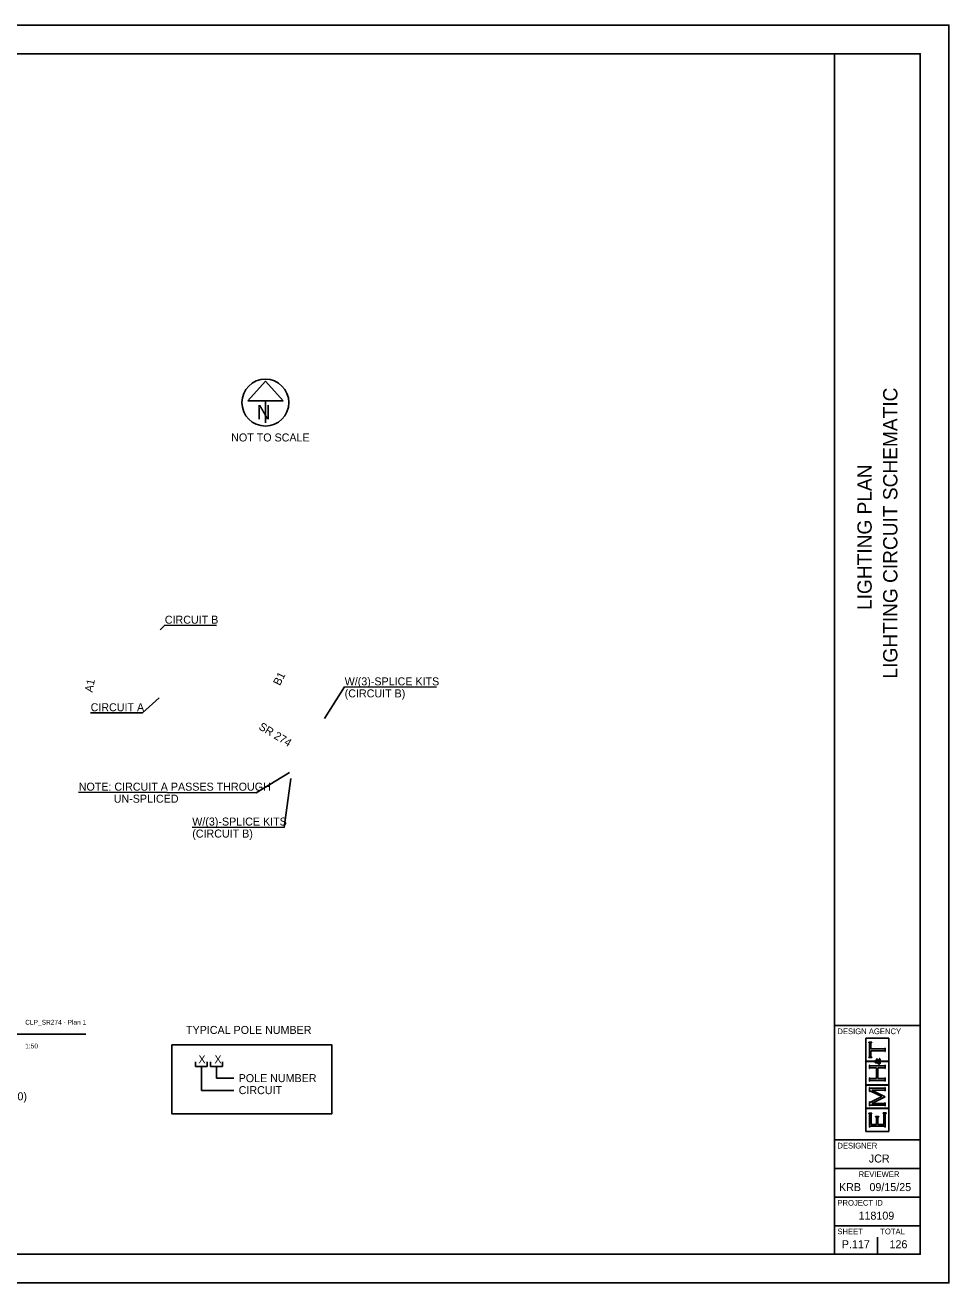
# Model space of a CAD drawing. Extents: x 0 to 34, y 0 to 22.
# Drawn here: x 17.84 to 34, y 0 to 22 of the extents above; entities that cross this region are included whole.
import ezdxf

# ---------------------------------------------------------------- set-up
doc = ezdxf.new("R2010")
doc.units = 0
for name, color, linetype in [('_CIVIL_CONSTRUCTION', 7, 'Continuous'), ('GE_P_Alignment', 7, 'Continuous'), ('PF_P_Grade_Line', 7, 'Continuous'), ('PF_X_Ground_Line', 7, 'Continuous'), ('SC_Scratch1', 7, 'Continuous'), ('SC_Scratch7', 7, 'Continuous')]:
    doc.layers.add(name, color=color, linetype=linetype)

msp = doc.modelspace()

# ---------------------------------------------------------------- linework, layer by layer
at = {"layer": '_CIVIL_CONSTRUCTION'}
for p, q in [((32, 0.5), (32, 21.5)), ((32, 4.5), (33.5, 4.5)), ((32, 2.5), (33.5, 2.5)), ((32, 2), (33.5, 2)), ((32, 1.5), (33.5, 1.5)), ((32, 1), (33.5, 1))]:
    msp.add_line(p, q, dxfattribs=at)
msp.add_lwpolyline([(1.5, 21.5), (33.5, 21.5), (33.5, 0.5), (1.5, 0.5)], close=True, dxfattribs=at)
at = {"layer": 'GE_P_Alignment'}
msp.add_lwpolyline([(0, 0), (34, 0), (34, 22), (0, 22)], close=True, dxfattribs=at)
at = {"layer": 'PF_P_Grade_Line'}
for p, q in [((22.043, 15.772), (21.735, 15.431)), ((22.35, 15.43), (22.043, 15.772)), ((21.735, 15.431), (22.35, 15.43)), ((22.042, 15.43), (22.041, 15.044)), ((20.28, 11.503), (20.201, 11.422)), ((21.188, 11.5), (20.28, 11.503)), ((23.427, 10.424), (23.078, 9.874)), ((25.037, 10.419), (23.427, 10.424)), ((19.89, 9.968), (20.185, 10.235)), ((19.89, 9.968), (18.982, 9.971)), ((21.881, 8.569), (22.463, 8.926)), ((22.37, 7.967), (22.486, 8.823)), ((21.881, 8.569), (18.774, 8.582)), ((22.37, 7.967), (20.759, 7.971)), ((20.818, 3.867), (20.818, 3.786)), ((20.818, 3.786), (21.025, 3.786)), ((20.921, 3.786), (20.921, 3.363)), ((21.025, 3.867), (21.025, 3.786)), ((21.084, 3.865), (21.084, 3.784)), ((21.084, 3.784), (21.29, 3.784)), ((21.187, 3.784), (21.187, 3.578)), ((21.29, 3.865), (21.29, 3.784)), ((21.187, 3.578), (21.488, 3.578)), ((20.921, 3.363), (21.488, 3.363))]:
    msp.add_line(p, q, dxfattribs=at)
msp.add_lwpolyline([(20.407, 4.166), (23.202, 4.166), (23.202, 2.955), (20.407, 2.955)], close=True, dxfattribs=at)
msp.add_circle((22.042, 15.398), 0.41, dxfattribs=at)
at = {"layer": 'PF_X_Ground_Line'}
for p, q in [((32.952, 4.279), (32.547, 4.279)), ((32.547, 4.279), (32.547, 3.875)), ((32.598, 4.204), (32.598, 4.211)), ((32.598, 4.211), (32.65, 4.211)), ((32.603, 4.203), (32.598, 4.204)), ((32.606, 4.201), (32.603, 4.203)), ((32.608, 4.199), (32.606, 4.201)), ((32.61, 4.196), (32.608, 4.199)), ((32.611, 4.192), (32.61, 4.196)), ((32.611, 4.187), (32.611, 4.192)), ((32.611, 3.968), (32.611, 4.187)), ((32.638, 4.196), (32.637, 4.192)), ((32.637, 4.192), (32.637, 4.187)), ((32.637, 4.187), (32.637, 4.093)), ((32.64, 4.199), (32.638, 4.196)), ((32.642, 4.201), (32.64, 4.199)), ((32.645, 4.203), (32.642, 4.201)), ((32.65, 4.204), (32.645, 4.203)), ((32.65, 4.211), (32.65, 4.204)), ((32.952, 3.875), (32.952, 4.279)), ((32.61, 3.958), (32.611, 3.962)), ((32.611, 3.962), (32.611, 3.968)), ((32.637, 4.093), (32.864, 4.093)), ((32.864, 4.061), (32.637, 4.061)), ((32.637, 4.061), (32.637, 3.968)), ((32.637, 3.968), (32.637, 3.962)), ((32.637, 3.962), (32.638, 3.958)), ((32.864, 4.093), (32.869, 4.093)), ((32.87, 4.061), (32.864, 4.061)), ((32.869, 4.093), (32.873, 4.094)), ((32.874, 4.06), (32.87, 4.061)), ((32.873, 4.094), (32.876, 4.096)), ((32.876, 4.059), (32.874, 4.06)), ((32.876, 4.096), (32.878, 4.097)), ((32.878, 4.057), (32.876, 4.059)), ((32.878, 4.097), (32.88, 4.101)), ((32.88, 4.053), (32.878, 4.057)), ((32.88, 4.101), (32.881, 4.106)), ((32.881, 4.048), (32.88, 4.053)), ((32.881, 4.106), (32.888, 4.106)), ((32.888, 4.048), (32.881, 4.048)), ((32.888, 4.106), (32.888, 4.048)), ((32.547, 3.875), (32.696, 3.875)), ((32.696, 3.869), (32.547, 3.869)), ((32.547, 3.869), (32.547, 3.465)), ((32.598, 3.95), (32.603, 3.951)), ((32.598, 3.944), (32.598, 3.95)), ((32.65, 3.944), (32.598, 3.944)), ((32.603, 3.951), (32.606, 3.953)), ((32.606, 3.953), (32.608, 3.955)), ((32.608, 3.955), (32.61, 3.958)), ((32.611, 3.749), (32.611, 3.807)), ((32.611, 3.807), (32.617, 3.807)), ((32.617, 3.749), (32.611, 3.749)), ((32.617, 3.807), (32.619, 3.802)), ((32.618, 3.754), (32.617, 3.749)), ((32.62, 3.758), (32.618, 3.754)), ((32.619, 3.802), (32.62, 3.798)), ((32.62, 3.798), (32.623, 3.797)), ((32.623, 3.76), (32.62, 3.758)), ((32.623, 3.797), (32.625, 3.795)), ((32.625, 3.761), (32.623, 3.76)), ((32.625, 3.795), (32.629, 3.794)), ((32.629, 3.762), (32.625, 3.761)), ((32.629, 3.794), (32.635, 3.794)), ((32.635, 3.762), (32.629, 3.762)), ((32.635, 3.794), (32.864, 3.794)), ((32.732, 3.762), (32.635, 3.762)), ((32.638, 3.958), (32.64, 3.955)), ((32.64, 3.955), (32.642, 3.953)), ((32.642, 3.953), (32.645, 3.951)), ((32.645, 3.951), (32.65, 3.95)), ((32.65, 3.95), (32.65, 3.944)), ((32.696, 3.875), (32.696, 3.869)), ((32.703, 3.879), (32.705, 3.883)), ((32.703, 3.873), (32.703, 3.879)), ((32.703, 3.868), (32.703, 3.873)), ((32.705, 3.863), (32.703, 3.868)), ((32.705, 3.883), (32.708, 3.887)), ((32.708, 3.858), (32.705, 3.863)), ((32.708, 3.887), (32.711, 3.89)), ((32.709, 3.879), (32.708, 3.876)), ((32.708, 3.876), (32.708, 3.873)), ((32.708, 3.873), (32.708, 3.869)), ((32.708, 3.869), (32.71, 3.866)), ((32.712, 3.853), (32.708, 3.858)), ((32.712, 3.881), (32.709, 3.879)), ((32.71, 3.866), (32.712, 3.864)), ((32.711, 3.89), (32.715, 3.892)), ((32.714, 3.883), (32.712, 3.881)), ((32.712, 3.864), (32.715, 3.862)), ((32.718, 3.85), (32.712, 3.853)), ((32.716, 3.884), (32.714, 3.883)), ((32.715, 3.892), (32.72, 3.892)), ((32.715, 3.862), (32.718, 3.861)), ((32.72, 3.884), (32.716, 3.884)), ((32.718, 3.861), (32.721, 3.861)), ((32.726, 3.85), (32.718, 3.85)), ((32.72, 3.892), (32.725, 3.892)), ((32.724, 3.884), (32.72, 3.884)), ((32.721, 3.861), (32.723, 3.861)), ((32.723, 3.861), (32.725, 3.862)), ((32.728, 3.882), (32.724, 3.884)), ((32.725, 3.892), (32.729, 3.89)), ((32.725, 3.862), (32.728, 3.862)), ((32.729, 3.85), (32.726, 3.85)), ((32.731, 3.88), (32.728, 3.882)), ((32.728, 3.862), (32.731, 3.863)), ((32.729, 3.89), (32.732, 3.887)), ((32.731, 3.85), (32.729, 3.85)), ((32.734, 3.877), (32.731, 3.88)), ((32.731, 3.863), (32.735, 3.865)), ((32.734, 3.851), (32.731, 3.85)), ((32.732, 3.887), (32.736, 3.883)), ((32.732, 3.572), (32.732, 3.762)), ((32.737, 3.872), (32.734, 3.877)), ((32.737, 3.852), (32.734, 3.851)), ((32.735, 3.865), (32.74, 3.867)), ((32.736, 3.883), (32.74, 3.878)), ((32.74, 3.867), (32.737, 3.872)), ((32.741, 3.853), (32.737, 3.852)), ((32.738, 3.893), (32.738, 3.922)), ((32.738, 3.922), (32.741, 3.922)), ((32.741, 3.893), (32.738, 3.893)), ((32.74, 3.878), (32.744, 3.869)), ((32.741, 3.922), (32.741, 3.918)), ((32.741, 3.918), (32.742, 3.915)), ((32.742, 3.896), (32.741, 3.895)), ((32.741, 3.895), (32.741, 3.893)), ((32.746, 3.855), (32.741, 3.853)), ((32.742, 3.915), (32.743, 3.913)), ((32.743, 3.897), (32.742, 3.896)), ((32.743, 3.913), (32.745, 3.911)), ((32.745, 3.899), (32.743, 3.897)), ((32.744, 3.869), (32.754, 3.875)), ((32.745, 3.911), (32.749, 3.908)), ((32.746, 3.899), (32.745, 3.899)), ((32.748, 3.899), (32.746, 3.899)), ((32.752, 3.844), (32.746, 3.855)), ((32.755, 3.899), (32.748, 3.899)), ((32.749, 3.908), (32.756, 3.904)), ((32.756, 3.86), (32.751, 3.857)), ((32.751, 3.857), (32.754, 3.852)), ((32.757, 3.837), (32.752, 3.844)), ((32.754, 3.875), (32.764, 3.881)), ((32.754, 3.852), (32.757, 3.848)), ((32.763, 3.895), (32.755, 3.899)), ((32.756, 3.904), (32.763, 3.9)), ((32.761, 3.863), (32.756, 3.86)), ((32.757, 3.848), (32.761, 3.845)), ((32.763, 3.833), (32.757, 3.837)), ((32.864, 3.762), (32.759, 3.762)), ((32.759, 3.762), (32.759, 3.572)), ((32.764, 3.865), (32.761, 3.863)), ((32.761, 3.845), (32.765, 3.843)), ((32.763, 3.9), (32.77, 3.896)), ((32.772, 3.887), (32.763, 3.895)), ((32.768, 3.829), (32.763, 3.833)), ((32.764, 3.881), (32.772, 3.887)), ((32.768, 3.867), (32.764, 3.865)), ((32.765, 3.843), (32.769, 3.841)), ((32.774, 3.872), (32.768, 3.867)), ((32.774, 3.827), (32.768, 3.829)), ((32.769, 3.841), (32.773, 3.841)), ((32.77, 3.896), (32.776, 3.891)), ((32.773, 3.841), (32.778, 3.841)), ((32.782, 3.878), (32.774, 3.872)), ((32.779, 3.827), (32.774, 3.827)), ((32.776, 3.891), (32.781, 3.895)), ((32.778, 3.841), (32.782, 3.843)), ((32.779, 3.923), (32.781, 3.926)), ((32.782, 3.922), (32.779, 3.923)), ((32.785, 3.827), (32.779, 3.827)), ((32.781, 3.926), (32.787, 3.924)), ((32.781, 3.895), (32.784, 3.898)), ((32.785, 3.921), (32.782, 3.922)), ((32.786, 3.873), (32.782, 3.878)), ((32.782, 3.843), (32.786, 3.846)), ((32.784, 3.898), (32.786, 3.901)), ((32.786, 3.919), (32.785, 3.921)), ((32.79, 3.829), (32.785, 3.827)), ((32.788, 3.917), (32.786, 3.919)), ((32.786, 3.901), (32.788, 3.904)), ((32.791, 3.886), (32.786, 3.881)), ((32.786, 3.881), (32.791, 3.876)), ((32.788, 3.869), (32.786, 3.873)), ((32.786, 3.846), (32.789, 3.849)), ((32.787, 3.924), (32.792, 3.921)), ((32.789, 3.914), (32.788, 3.917)), ((32.788, 3.904), (32.789, 3.908)), ((32.79, 3.867), (32.788, 3.869)), ((32.789, 3.911), (32.789, 3.914)), ((32.789, 3.908), (32.789, 3.911)), ((32.789, 3.849), (32.791, 3.853)), ((32.791, 3.864), (32.79, 3.867)), ((32.793, 3.834), (32.79, 3.829)), ((32.794, 3.89), (32.791, 3.886)), ((32.791, 3.876), (32.795, 3.87)), ((32.791, 3.861), (32.791, 3.864)), ((32.791, 3.859), (32.791, 3.861)), ((32.791, 3.853), (32.791, 3.859)), ((32.792, 3.921), (32.795, 3.918)), ((32.797, 3.838), (32.793, 3.834)), ((32.796, 3.894), (32.794, 3.89)), ((32.795, 3.918), (32.798, 3.914)), ((32.795, 3.87), (32.797, 3.866)), ((32.798, 3.897), (32.796, 3.894)), ((32.797, 3.866), (32.798, 3.861)), ((32.799, 3.844), (32.797, 3.838)), ((32.798, 3.914), (32.799, 3.91)), ((32.799, 3.901), (32.798, 3.897)), ((32.798, 3.861), (32.799, 3.857)), ((32.799, 3.91), (32.799, 3.905)), ((32.799, 3.905), (32.799, 3.901)), ((32.803, 3.869), (32.799, 3.875)), ((32.799, 3.875), (32.952, 3.875)), ((32.799, 3.857), (32.799, 3.852)), ((32.799, 3.852), (32.799, 3.844)), ((32.952, 3.869), (32.803, 3.869)), ((32.864, 3.794), (32.869, 3.794)), ((32.87, 3.762), (32.864, 3.762)), ((32.869, 3.794), (32.873, 3.795)), ((32.874, 3.761), (32.87, 3.762)), ((32.873, 3.795), (32.876, 3.797)), ((32.876, 3.76), (32.874, 3.761)), ((32.876, 3.797), (32.878, 3.798)), ((32.878, 3.758), (32.876, 3.76)), ((32.878, 3.798), (32.88, 3.802)), ((32.88, 3.754), (32.878, 3.758)), ((32.88, 3.802), (32.881, 3.807)), ((32.881, 3.749), (32.88, 3.754)), ((32.881, 3.807), (32.888, 3.807)), ((32.888, 3.749), (32.881, 3.749)), ((32.888, 3.807), (32.888, 3.749)), ((32.952, 3.465), (32.952, 3.869)), ((32.611, 3.527), (32.611, 3.585)), ((32.611, 3.585), (32.617, 3.585)), ((32.617, 3.527), (32.611, 3.527)), ((32.617, 3.585), (32.619, 3.58)), ((32.618, 3.532), (32.617, 3.527)), ((32.62, 3.536), (32.618, 3.532)), ((32.619, 3.58), (32.62, 3.576)), ((32.62, 3.576), (32.623, 3.574)), ((32.623, 3.537), (32.62, 3.536)), ((32.623, 3.574), (32.625, 3.573)), ((32.625, 3.539), (32.623, 3.537)), ((32.625, 3.573), (32.629, 3.572)), ((32.629, 3.54), (32.625, 3.539)), ((32.629, 3.572), (32.635, 3.572)), ((32.635, 3.54), (32.629, 3.54)), ((32.635, 3.572), (32.732, 3.572)), ((32.864, 3.54), (32.635, 3.54)), ((32.759, 3.572), (32.864, 3.572)), ((32.864, 3.572), (32.87, 3.572)), ((32.87, 3.54), (32.864, 3.54)), ((32.87, 3.572), (32.874, 3.573)), ((32.874, 3.539), (32.87, 3.54)), ((32.874, 3.573), (32.876, 3.574)), ((32.876, 3.538), (32.874, 3.539)), ((32.876, 3.574), (32.878, 3.576)), ((32.878, 3.536), (32.876, 3.538)), ((32.878, 3.576), (32.88, 3.58)), ((32.88, 3.532), (32.878, 3.536)), ((32.88, 3.58), (32.881, 3.585)), ((32.881, 3.527), (32.88, 3.532)), ((32.881, 3.585), (32.888, 3.585)), ((32.888, 3.527), (32.881, 3.527)), ((32.888, 3.585), (32.888, 3.527)), ((32.547, 3.465), (32.952, 3.465)), ((32.952, 3.459), (32.547, 3.459)), ((32.547, 3.459), (32.547, 3.055)), ((32.611, 3.345), (32.611, 3.418)), ((32.611, 3.418), (32.617, 3.418)), ((32.617, 3.345), (32.611, 3.345)), ((32.617, 3.418), (32.619, 3.412)), ((32.62, 3.352), (32.617, 3.345)), ((32.619, 3.412), (32.62, 3.409)), ((32.62, 3.409), (32.623, 3.407)), ((32.622, 3.355), (32.62, 3.352)), ((32.626, 3.355), (32.622, 3.355)), ((32.623, 3.407), (32.625, 3.405)), ((32.625, 3.405), (32.629, 3.405)), ((32.629, 3.355), (32.626, 3.355)), ((32.629, 3.405), (32.635, 3.405)), ((32.633, 3.353), (32.629, 3.355)), ((32.64, 3.35), (32.633, 3.353)), ((32.635, 3.405), (32.864, 3.405)), ((32.825, 3.257), (32.64, 3.35)), ((32.864, 3.373), (32.654, 3.373)), ((32.654, 3.373), (32.888, 3.255)), ((32.75, 3.5), (32.75, 3.5)), ((32.864, 3.405), (32.869, 3.405)), ((32.87, 3.373), (32.864, 3.373)), ((32.869, 3.405), (32.873, 3.405)), ((32.874, 3.372), (32.87, 3.373)), ((32.873, 3.405), (32.876, 3.407)), ((32.876, 3.37), (32.874, 3.372)), ((32.876, 3.407), (32.878, 3.409)), ((32.878, 3.369), (32.876, 3.37)), ((32.878, 3.409), (32.88, 3.412)), ((32.88, 3.365), (32.878, 3.369)), ((32.88, 3.412), (32.881, 3.418)), ((32.881, 3.36), (32.88, 3.365)), ((32.881, 3.418), (32.888, 3.418)), ((32.888, 3.36), (32.881, 3.36)), ((32.888, 3.418), (32.888, 3.36)), ((32.952, 3.055), (32.952, 3.459)), ((32.611, 3.096), (32.611, 3.168)), ((32.611, 3.168), (32.617, 3.168)), ((32.617, 3.096), (32.611, 3.096)), ((32.617, 3.168), (32.62, 3.162)), ((32.618, 3.102), (32.617, 3.096)), ((32.62, 3.105), (32.618, 3.102)), ((32.62, 3.162), (32.622, 3.158)), ((32.623, 3.107), (32.62, 3.105)), ((32.622, 3.158), (32.626, 3.158)), ((32.625, 3.109), (32.623, 3.107)), ((32.629, 3.109), (32.625, 3.109)), ((32.626, 3.158), (32.627, 3.158)), ((32.627, 3.158), (32.633, 3.161)), ((32.635, 3.109), (32.629, 3.109)), ((32.633, 3.161), (32.641, 3.165)), ((32.864, 3.109), (32.635, 3.109)), ((32.641, 3.165), (32.825, 3.257)), ((32.888, 3.255), (32.654, 3.138)), ((32.654, 3.138), (32.864, 3.138)), ((32.864, 3.138), (32.869, 3.138)), ((32.87, 3.109), (32.864, 3.109)), ((32.869, 3.138), (32.873, 3.139)), ((32.874, 3.109), (32.87, 3.109)), ((32.873, 3.139), (32.876, 3.141)), ((32.876, 3.107), (32.874, 3.109)), ((32.876, 3.141), (32.878, 3.143)), ((32.878, 3.105), (32.876, 3.107)), ((32.878, 3.143), (32.88, 3.146)), ((32.88, 3.102), (32.878, 3.105)), ((32.88, 3.146), (32.881, 3.151)), ((32.881, 3.096), (32.88, 3.102)), ((32.881, 3.151), (32.888, 3.151)), ((32.888, 3.096), (32.881, 3.096)), ((32.888, 3.151), (32.888, 3.096)), ((32.547, 3.055), (32.952, 3.055)), ((32.952, 3.049), (32.547, 3.049)), ((32.547, 3.049), (32.547, 2.645)), ((32.598, 2.962), (32.598, 2.969)), ((32.598, 2.969), (32.65, 2.969)), ((32.603, 2.961), (32.598, 2.962)), ((32.606, 2.959), (32.603, 2.961)), ((32.608, 2.957), (32.606, 2.959)), ((32.61, 2.955), (32.608, 2.957)), ((32.611, 2.951), (32.61, 2.955)), ((32.611, 2.945), (32.611, 2.951)), ((32.611, 2.725), (32.611, 2.945)), ((32.64, 2.957), (32.638, 2.955)), ((32.638, 2.955), (32.638, 2.951)), ((32.638, 2.951), (32.638, 2.945)), ((32.638, 2.945), (32.638, 2.77)), ((32.642, 2.959), (32.64, 2.957)), ((32.645, 2.961), (32.642, 2.959)), ((32.65, 2.962), (32.645, 2.961)), ((32.65, 2.969), (32.65, 2.962)), ((32.719, 2.902), (32.719, 2.908)), ((32.719, 2.908), (32.772, 2.908)), ((32.724, 2.901), (32.719, 2.902)), ((32.728, 2.899), (32.724, 2.901)), ((32.729, 2.896), (32.728, 2.899)), ((32.731, 2.894), (32.729, 2.896)), ((32.732, 2.89), (32.731, 2.894)), ((32.732, 2.884), (32.732, 2.89)), ((32.732, 2.77), (32.732, 2.884)), ((32.76, 2.894), (32.759, 2.89)), ((32.759, 2.89), (32.759, 2.884)), ((32.759, 2.884), (32.759, 2.77)), ((32.761, 2.896), (32.76, 2.894)), ((32.763, 2.899), (32.761, 2.896)), ((32.767, 2.901), (32.763, 2.899)), ((32.772, 2.902), (32.767, 2.901)), ((32.772, 2.908), (32.772, 2.902)), ((32.848, 2.965), (32.848, 2.972)), ((32.848, 2.972), (32.901, 2.972)), ((32.853, 2.964), (32.848, 2.965)), ((32.857, 2.962), (32.853, 2.964)), ((32.859, 2.96), (32.857, 2.962)), ((32.86, 2.958), (32.859, 2.96)), ((32.861, 2.953), (32.86, 2.958)), ((32.861, 2.948), (32.861, 2.953)), ((32.861, 2.77), (32.861, 2.948)), ((32.889, 2.957), (32.888, 2.953)), ((32.888, 2.953), (32.888, 2.948)), ((32.888, 2.948), (32.888, 2.725)), ((32.891, 2.96), (32.889, 2.957)), ((32.892, 2.962), (32.891, 2.96)), ((32.896, 2.964), (32.892, 2.962)), ((32.901, 2.965), (32.896, 2.964)), ((32.901, 2.972), (32.901, 2.965)), ((32.952, 2.645), (32.952, 3.049)), ((32.547, 2.645), (32.952, 2.645)), ((32.617, 2.725), (32.611, 2.725)), ((32.619, 2.73), (32.617, 2.725)), ((32.62, 2.734), (32.619, 2.73)), ((32.623, 2.735), (32.62, 2.734)), ((32.625, 2.737), (32.623, 2.735)), ((32.629, 2.738), (32.625, 2.737)), ((32.635, 2.738), (32.629, 2.738)), ((32.864, 2.738), (32.635, 2.738)), ((32.638, 2.77), (32.732, 2.77)), ((32.759, 2.77), (32.861, 2.77)), ((32.87, 2.738), (32.864, 2.738)), ((32.874, 2.737), (32.87, 2.738)), ((32.876, 2.735), (32.874, 2.737)), ((32.878, 2.734), (32.876, 2.735)), ((32.88, 2.73), (32.878, 2.734)), ((32.881, 2.725), (32.88, 2.73)), ((32.888, 2.725), (32.881, 2.725)), ((32.375, 0.675), (32.375, 0.675)), ((32.75, 0.5), (32.75, 0.8))]:
    msp.add_line(p, q, dxfattribs=at)
at = {"layer": 'SC_Scratch1'}
msp.add_line((17.176, 4.351), (18.898, 4.351), dxfattribs=at)
at = {"layer": 'SC_Scratch7'}
msp.add_circle((22.042, 15.398), 0.41, dxfattribs=at)

# ---------------------------------------------------------------- texts
at = {"layer": 'PF_P_Grade_Line'}
for s, height, rotation, p in [('N', 0.25, 359.8697, (21.89, 15.107)), ('NOT TO SCALE', 0.14, 0, (21.443, 14.718)), ('CIRCUIT B', 0.14, 0, (20.282, 11.53)), ('B1', 0.14, 63.0724, (22.295, 10.436)), ('W/(3)-SPLICE KITS', 0.14, 0, (23.429, 10.451)), ('A1', 0.14, 78.6502, (19.015, 10.322)), ('(CIRCUIT B)', 0.14, 0, (23.429, 10.241)), ('CIRCUIT A', 0.14, 0, (18.984, 9.998)), ('SR 274', 0.14, 328.8039, (21.912, 9.693)), ('NOTE: CIRCUIT A PASSES THROUGH', 0.14, 0, (18.776, 8.609)), (' UN-SPLICED', 0.14, 0, (19.336, 8.399)), ('W/(3)-SPLICE KITS', 0.14, 0, (20.762, 7.999)), ('(CIRCUIT B)', 0.14, 0, (20.762, 7.789)), ('TYPICAL POLE NUMBER ', 0.14, 0, (20.653, 4.354)), ('X   X', 0.14, 0, (20.87, 3.841)), ('POLE NUMBER', 0.14, 0, (21.574, 3.511)), ('PROPOSED 120/240V POWER SERVICE (GROUND MOUNTED ODOT HL-40.20)', 0.14, 0, (10.9, 3.193)), ('CIRCUIT', 0.14, 0, (21.574, 3.301))]:
    msp.add_text(s, height=height, rotation=rotation, dxfattribs=at).set_placement(p)
at = {"layer": 'PF_X_Ground_Line'}
for s, p in [('LIGHTING CIRCUIT SCHEMATIC ', (33.1, 10.571)), ('LIGHTING PLAN', (32.65, 11.77))]:
    msp.add_text(s, height=0.25, rotation=90, dxfattribs=at).set_placement(p)
for s, height, p in [('DESIGN AGENCY', 0.1, (32.05, 4.35)), ('DESIGNER', 0.1, (32.05, 2.35)), ('JCR', 0.14, (32.6, 2.105)), ('REVIEWER', 0.1, (32.422, 1.85)), ('KRB', 0.14, (32.078, 1.605)), ('09/15/25', 0.14, (32.611, 1.605)), ('PROJECT ID', 0.1, (32.05, 1.35)), ('118109', 0.14, (32.42, 1.105)), ('SHEET', 0.1, (32.05, 0.85)), ('TOTAL', 0.1, (32.8, 0.85)), ('P.117', 0.14, (32.128, 0.605)), ('126', 0.14, (32.962, 0.605))]:
    msp.add_text(s, height=height, dxfattribs=at).set_placement(p)
at = {"layer": 'SC_Scratch1'}
for s, height, p in [('CLP_SR274 - Plan 1', 0.08333, (17.839, 4.517)), ('1:50', 0.0833, (17.839, 4.101))]:
    msp.add_text(s, height=height, dxfattribs=at).set_placement(p)

doc.saveas('drawing.dxf')
